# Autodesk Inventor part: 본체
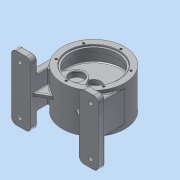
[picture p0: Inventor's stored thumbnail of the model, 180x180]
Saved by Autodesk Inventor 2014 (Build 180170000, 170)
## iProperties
Created: 2025-12
Part Number: 본체
Material: 알루미늄 6061
Document SubType Name: Modeling
Designer: dg
Density: 2.71 g/cm^3
Appearance: 알루미늄 - 평지
Mass: 5646.09 g
Surface Area: 3060.39 cm^2
Volume: 2083.43 cm^3
Author: dg
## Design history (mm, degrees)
sketch "스케치1"
  geometry: C1 r 97 at (0, 0); 1 further point
  constraints: 1 centre point, 1 coincident
  dimensions: "d0" = 194 diameter of C1
extrude "돌출1" new body sketch "스케치1" stored distance "d1" = 124; taper "d2" = 0 deg
sketch "스케치2"
  geometry: L1 (97, 62)-(-97, 62) reference; L2 (-97, -62)-(97, -62) reference; L3 (0, 62)-(0, -62); L4 (0, 62)-(78, 62); L5 (78, 62)-(78, 57); L6 (78, 57)-(73, 57); L7 (73, 57)-(73, 40); L8 (73, 40)-(87, 40); L9 (87, 40)-(87, 8); L10 (87, 8)-(21, 8); L11 (21, 8)-(21, -4); L12 (21, -4)-(19, -4); L13 (19, -4)-(19, -8); L14 (19, -8)-(87, -8); L15 (87, -8)-(87, -40); L16 (87, -40)-(73, -40); L17 (73, -40)-(73, -57); L18 (73, -57)-(78, -57); L19 (78, -57)-(78, -62); L20 (78, -62)-(0, -62); 1 further point
  constraints: 36 end point, 12 parallel, 4 perpendicular, 3 collinear, 3 vertical alignment, 2 midpoint, 2 point on line
  dimensions: "d3" = 156 diameter of L5 L3; "d4" = 146 diameter of L7 L3; "d5" = 174 diameter of L9 L3; "d6" = 5 distance of L4.end L5.end; "d8" = 32 distance of L8.end L9.end; "d9" = 22 distance between parallel lines of L8 L1; "d10" = 66 distance between parallel lines of L12 L1; "d11" = 42 diameter of L11 L3; "d12" = 38 diameter of L13 L3
revolve "회전1" sketch "스케치2" stored, may be unused: angle "d13" = 90 deg
sketch "스케치3"
  geometry: L1 (-23.383, -39)-(-37.148, -62.842); L2 (23.383, -39)-(37.148, -62.842); L3 (0, -52.5)-(0, -73); C1 r 78 at (0, 0) reference; A1 r 73 centre (0, 0) between (-37.148, -62.842) and (37.148, -62.842) reference; A2 r 27 centre (0, -52.5) between (23.383, -39) and (-23.383, -39)
  constraints: 6 end point, 5 point on circle, 2 tangent, 1 centre point, 1 vertical, 1 vertical alignment
  dimensions: "d14" = 52.5 distance of L3.start C1.centre; "d15" = 27 radius of A2; "d16" = 30 deg angle of L3 L2; "d17" = 30 deg angle of L3 L1
extrude "돌출2" join sketch "스케치3" distance "d18" = 17; taper "d19" = 0 deg
sketch "스케치4"
  geometry: L1 (-25.5, 57)-(-39, 57) reference; L2 (-39, 57)-(-62.842, 57) reference; L3 (78, 57)-(-78, 57) reference; L4 (87, -8)-(-87, -8) reference; L5 (-52.5, 57)-(-52.5, -8); L6 (-52.5, -8)-(-33.5, -8); L7 (-33.5, -8)-(-33.5, -4); L8 (-33.5, -4)-(-31.5, -4); L9 (87, 8)-(-87, 8) reference; L10 (-31.5, -4)-(-31.5, 8); L11 (-31.5, 8)-(-52.5, 8); L12 (-78, 62)-(78, 62) reference; L13 (-52.5, 57)-(-31.5, 57); L14 (-31.5, 57)-(-31.5, 53.95); L15 (-31.5, 53.95)-(-30.25, 53.95); L16 (-30.25, 53.95)-(-30.25, 52); L17 (-30.25, 52)-(-31.5, 52); L18 (-39, 40)-(-25.5, 40) reference; L19 (-62.842, 40)-(-39, 40) reference; L20 (-31.5, 52)-(-31.5, 40); L21 (-31.5, 40)-(-52.5, 40); 1 further point
  constraints: 26 end point, 10 point on line, 7 perpendicular, 2 parallel
  dimensions: "d20" = 52.5 distance from line of L5 point (0, 0); "d21" = 38 diameter of L7 L5; "d22" = 42 diameter of L10 L5; "d23" = 66 distance between parallel lines of L8 L12; "d24" = 42 diameter of L14 L5; "d25" = 44.5 diameter of L16 L5; "d26" = 1.95 distance of L15.end L16.end; "d27" = 12 distance of L17.end L20.end; "d28" = 42 diameter of L20 L5
revolve "회전2" sketch "스케치4" stored, may be unused: angle "d29" = 90 deg
sketch "스케치5"
  geometry: C1 r 78 at (0, 0) reference; 1 further point
  constraints: 1 vertical alignment
  dimensions: "d30" = 85 distance of C1.centre point (0, 85)
hole "구멍1" sketch "스케치5" at (0, 85) diameter "d31" = 6.917; stored, may be unused: countersink angle "d35" = 90 deg, drill point angle "d37" = 118 deg; dims "d32" = 16, "d33" = 4, "d34" = 2, "d36" = 18
node "작업 평면1"
sketch "스케치6"
  geometry: L1 (-97, -62)-(-97, 62) reference; L2 (97, -62)-(97, 62) reference; L3 (-75, 100)-(-135, 100); L4 (-135, 100)-(-135, -100); L5 (-135, -100)-(-75, -100); L6 (-75, -100)-(-75, 100); L7 (135, 100)-(75, 100); L8 (75, 100)-(75, -100); L9 (75, -100)-(135, -100); L10 (135, -100)-(135, 100); 3 further points
  constraints: 16 end point, 4 parallel, 2 equal length, 2 horizontal, 2 horizontal alignment, 2 midpoint, 2 perpendicular
  dimensions: "d42" = 150 distance between parallel lines of L8 L6; "d43" = 75 distance from line of point (0, 0) L6; "d44" = 60 distance of L3.start L3.end; "d45" = 200 distance of L3.end L4.end
extrude "돌출3" join sketch "스케치6" distance "d46" = 20; taper "d47" = 0 deg
fillet "모깎기1" dims "d48" = 15
sketch "스케치7"
  geometry: 3 further points
  constraints: 1 vertical alignment
  dimensions: "d49" = 150 distance of point (110, -75) point (110, 75); "d50" = 75 vertical distance of point (0, 0) point (110, 75); "d51" = 110 horizontal distance of point (110, 75) point (0, 0)
hole "구멍2" sketch "스케치7" at (110, -75), (110, 75) diameter "d52" = 13.5; stored, may be unused: countersink angle "d56" = 90 deg, drill point angle "d58" = 118 deg; dims "d53" = 16, "d54" = 33, "d55" = 2, "d57" = 18
sketch "스케치8"
  geometry: L1 (75, 85)-(75, -85) reference; L2 (75, 50)-(97, 50); L3 (97, 50)-(97, -50); L4 (97, -50)-(75, -50); L5 (75, -50)-(75, 50); 2 further points
  constraints: 8 end point, 2 parallel, 1 horizontal, 1 horizontal alignment, 1 midpoint, 1 perpendicular, 1 point on line
  dimensions: "d59" = 22 distance of L2.start L2.end; "d60" = 100 distance of L2.end L3.end
extrude "돌출4" join sketch "스케치8" stored distance "d61" = 20; taper "d62" = 0 deg
sketch "스케치9"
  geometry: L1 (75, -100)-(75, -61.514) reference; L2 (75, -120)-(75, -100) reference; L3 (36.6, -89.83)-(75, -112); A1 r 97 centre (0, 0) between (75, -61.514) and (36.6, -89.83) reference; 1 further point
  constraints: 2 end point, 1 point on circle, 1 point on line
  dimensions: "d63" = 8 distance of L3.end L2.start; "d64" = 60 deg angle of L3 L1
feature "리브1" sketch "스케치9" dims "d65" = 1, "d66" = 12, "d67" = 0, "d68" = 0, "d69" = 1, "d70" = 1
chamfer "모따기1" distance "d75" = 1; stored, may be unused: second distance "d76" = 2, angle "d77" = 45 deg
fillet "모깎기2" dims "d78" = 3
fillet "모깎기3" dims "d79" = 0.6
node "작업 평면3"
fillet "모깎기12" dims "d90" = 3
fillet "모깎기13" dims "d91" = 3
fillet "모깎기14" dims "d92" = 3
fillet "모깎기15" dims "d93" = 3
fillet "모깎기16" dims "d94" = 3
fillet "모깎기17" dims "d95" = 3
fillet "모깎기18" dims "d96" = 3
fillet "모깎기19" dims "d97" = 3
sketch "스케치13"
  geometry: 2 further points
  constraints: 1 coincident, 1 other
feature "엠보싱3" sketch "스케치13" dims "d3" = 156, "d4" = 146, "d5" = 174, "d6" = 5, "d8" = 32, "d9" = 22, "d10" = 66, "d11" = 42, "d12" = 38, "d98" = 0.5, "d99" = 0
fillet "모깎기21" dims "d103" = 3
fillet "모깎기22" dims "d106" = 3
node "솔리드1"
mirror "대칭1"
pattern_circular "원형 패턴1" dims angle "d39" = 360 deg
mirror "대칭2"
